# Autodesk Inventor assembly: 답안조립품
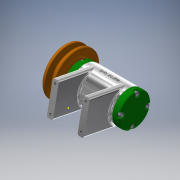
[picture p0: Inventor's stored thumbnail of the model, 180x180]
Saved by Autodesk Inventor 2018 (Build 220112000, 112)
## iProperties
Created: 2020-07
Part Number: 답안조립품
Material: 일반
Document SubType Name: Assembly
Designer: home
Author: home
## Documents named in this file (15)
- C:\Users\home\Desktop\700706V1030\답안조립품.iam
- C:\Users\home\Desktop\700706V1030\베어링 6002.ipt
- C:\Users\home\Desktop\700706V1030\본체.ipt
- C:\Users\home\Desktop\700706V1030\뒤커버.ipt
- C:\Users\home\Desktop\700706V1030\앞커버.ipt
- C:\Users\home\Desktop\700706V1030\축.ipt
- C:\Users\home\Desktop\700706V1030\오일 실 15 25 7.ipt
- C:\Users\home\Desktop\700706V1030\키 3x3x12.ipt
- C:\Users\home\Desktop\700706V1030\V벨트풀리.ipt
- C:\Users\home\Desktop\700706V1030\와셔 6x11.5.ipt
- C:\Users\home\Desktop\700706V1030\스프링와셔 8.ipt
- C:\Users\home\Desktop\700706V1030\너트 M8.ipt
- C:\Users\home\Desktop\700706V1030\볼트 M6x8.ipt
- C:\Users\home\Desktop\700706V1030\볼트 M4x12.ipt
- C:\Users\home\Desktop\700706V1030\와셔 8x17.ipt
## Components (1 placed, 1 different names)
1. V벨트풀리:1
